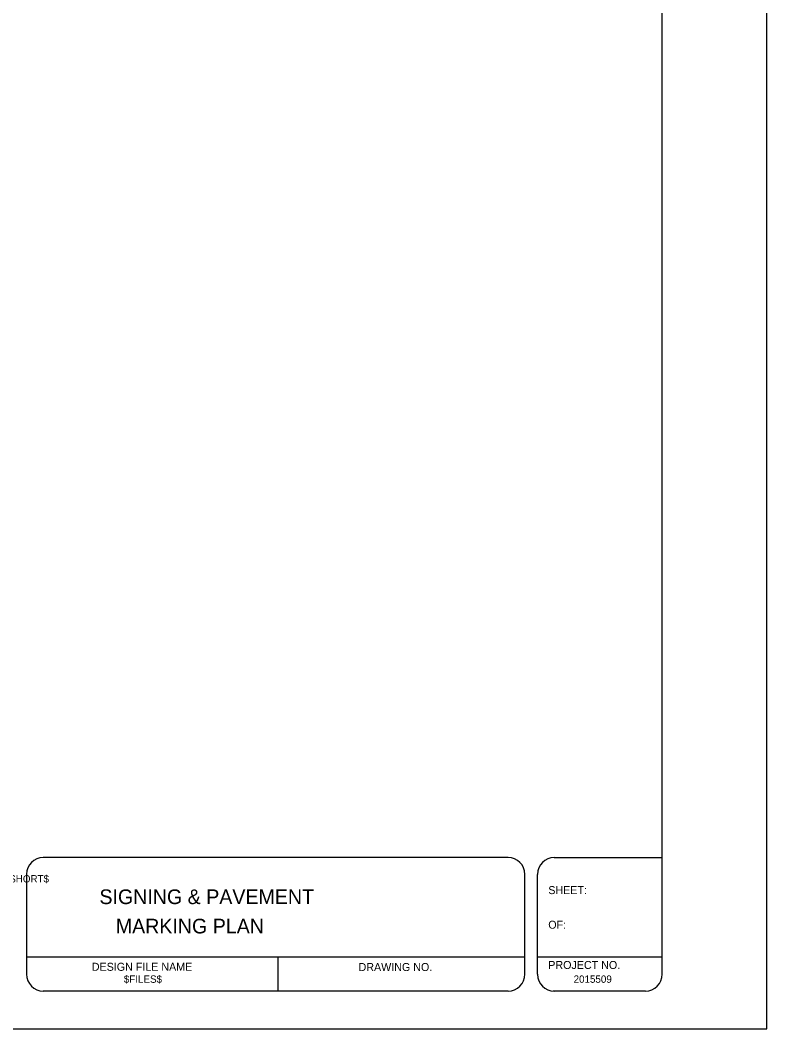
# Model space of a CAD drawing. Extents: x -0.7 to 16, y -0.9 to 9.7.
# Drawn here: x 12.02 to 15.95, y -0.9 to 4.4 of the extents above; entities that cross this region are included whole.
import ezdxf

# ---------------------------------------------------------------- set-up
doc = ezdxf.new("R2010")
doc.units = 0
doc.layers.add('Default', color=7, linetype='Continuous')
doc.layers.add('PlotBorder_dp', color=7, linetype='Continuous')

msp = doc.modelspace()

# ---------------------------------------------------------------- linework, layer by layer
at = {"layer": 'Default'}
for p, q in [((15.4, -0.6133), (15.4, 9.5065)), ((14.5898, 0), (12.146, 0)), ((14.8324, 0), (15.4, 0)), ((12.0578, -0.0882), (12.0578, -0.6131)), ((14.678, -0.6135), (14.678, -0.0884)), ((14.7442, -0.6135), (14.7442, -0.0884)), ((14.6769, -0.5241), (12.0568, -0.5241)), ((13.3801, -0.7005), (13.3801, -0.5241)), ((15.4, -0.5241), (14.7475, -0.5241)), ((14.5898, -0.7014), (12.146, -0.7014)), ((15.3118, -0.7015), (14.8271, -0.7015))]:
    msp.add_line(p, q, dxfattribs=at)
for centre, major_axis, start_param, end_param in [((12.146, -0.0882), (0, 0.0882), 0, 1.570796), ((14.5898, -0.0884), (0, 0.0882), 4.712389, 6.283185), ((14.8324, -0.0884), (0, -0.0882), 3.141593, 4.712389), ((12.146, -0.6131), (0, -0.0882), 4.712389, 6.283185), ((14.5898, -0.6131), (0, 0.0882), 3.141593, 4.712389), ((14.8324, -0.6135), (0, -0.0882), 4.712389, 6.283185), ((15.3118, -0.6133), (0, -0.0882), 0, 1.570796)]:
    msp.add_ellipse(centre, major_axis=major_axis, ratio=0.999927, start_param=start_param, end_param=end_param, dxfattribs=at)
at = {"layer": 'PlotBorder_dp'}
msp.add_lwpolyline([(-0.55, -0.9), (15.95, -0.9), (15.95, 9.7), (-0.55, 9.7)], close=True, dxfattribs=at)

# ---------------------------------------------------------------- texts
at = {"layer": 'Default'}
for s, height, p in [('$SCALESHORT$', 0.038546, (11.7691, -0.1311)), ('SHEET:', 0.04207, (14.8009, -0.1922)), ('   SIGNING & PAVEMENT   ', 0.077091, (12.3551, -0.2446)), ('      MARKING PLAN      ', 0.077091, (12.3551, -0.3988)), ('OF:', 0.04207, (14.8009, -0.374)), ('DESIGN FILE NAME', 0.042066, (12.4009, -0.5951)), ('DRAWING NO.', 0.042066, (13.8035, -0.5964)), ('PROJECT NO.', 0.042066, (14.8009, -0.5856)), ('$FILES$', 0.03855, (12.5694, -0.6581)), ('2015509', 0.03855, (14.9341, -0.6581))]:
    msp.add_text(s, height=height, dxfattribs=at).set_placement(p)

doc.saveas('drawing.dxf')
